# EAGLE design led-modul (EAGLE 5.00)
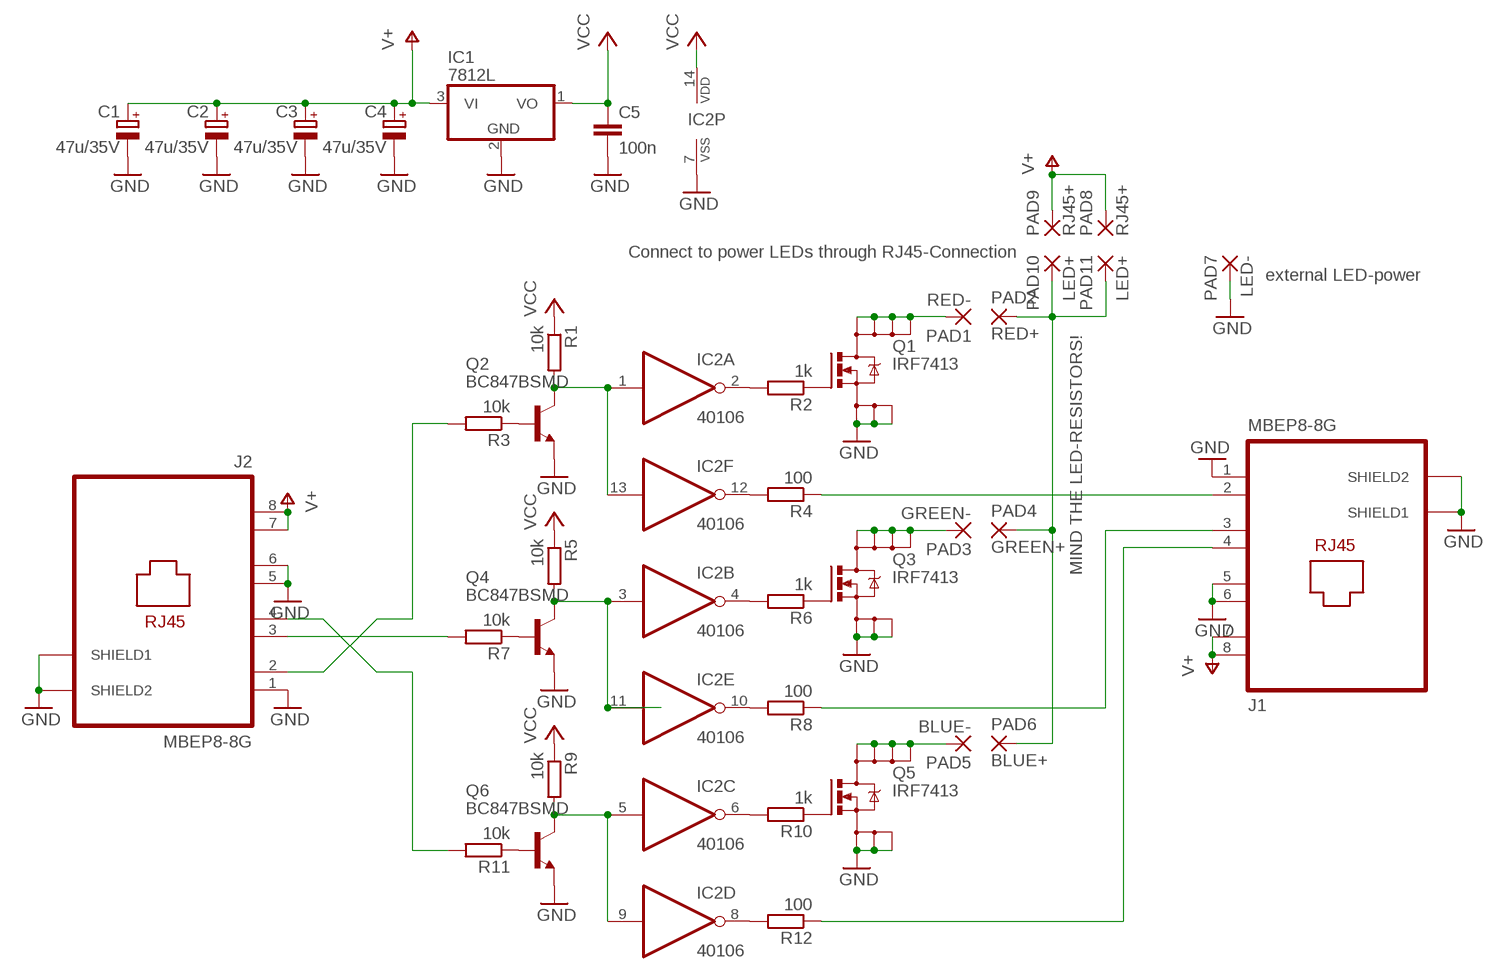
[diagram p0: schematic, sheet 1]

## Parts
C1  47u/35V  CPOL-EUE2-5  [E2-5]
C2  47u/35V  CPOL-EUE2-5  [E2-5]
C3  47u/35V  CPOL-EUE2-5  [E2-5]
C4  47u/35V  CPOL-EUE2-5  [E2-5]
C5  100n  C-EUC1206  [C1206]
IC1  7812L  [TO92]
IC2  40106  4584D  [SO14]
J1  MBEP8-8G  [MBEP8-8G]
J2  MBEP8-8G  [MBEP8-8G]
PAD1  RED-  2,54/1,1  [2,54/1,1]
PAD2  RED+  2,54/1,1  [2,54/1,1]
PAD3  GREEN-  2,54/1,1  [2,54/1,1]
PAD4  GREEN+  2,54/1,1  [2,54/1,1]
PAD5  BLUE-  2,54/1,1  [2,54/1,1]
PAD6  BLUE+  2,54/1,1  [2,54/1,1]
PAD7  LED-  2,54/1,1  [2,54/1,1]
PAD8  RJ45+  2,54/1,1  [2,54/1,1]
PAD9  RJ45+  2,54/1,1  [2,54/1,1]
PAD10  LED+  2,54/1,1  [2,54/1,1]
PAD11  LED+  2,54/1,1  [2,54/1,1]
Q1  IRF7413  [SO08]
Q2  BC847BSMD  [SOT23]
Q3  IRF7413  [SO08]
Q4  BC847BSMD  [SOT23]
Q5  IRF7413  [SO08]
Q6  BC847BSMD  [SOT23]
R1  10k  R-EU_R1206  [R1206]
R2  1k  R-EU_R1206  [R1206]
R3  10k  R-EU_R1206  [R1206]
R4  100  R-EU_R1206  [R1206]
R5  10k  R-EU_R1206  [R1206]
R6  1k  R-EU_R1206  [R1206]
R7  10k  R-EU_R1206  [R1206]
R8  100  R-EU_R1206  [R1206]
R9  10k  R-EU_R1206  [R1206]
R10  1k  R-EU_R1206  [R1206]
R11  10k  R-EU_R1206  [R1206]
R12  100  R-EU_R1206  [R1206]

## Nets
GND: C1.- C2.- C3.- C4.- C5.2 IC1.2(GND) IC2.7(P:VSS) J1.1 J1.5 J1.6 J1.S1(SHIELD1) J1.S2(SHIELD2) J2.1 J2.5 J2.6 J2.S1(SHIELD1) J2.S2(SHIELD2) PAD7.1(P) Q1.1(S) Q1.2(S) Q1.3(S) Q2.2(E) Q3.1(S) Q3.2(S) Q3.3(S) Q4.2(E) Q5.1(S) Q5.2(S) Q5.3(S) Q6.2(E)
LED+: PAD2.1(P) PAD4.1(P) PAD6.1(P) PAD10.1(P) PAD11.1(P)
N$1: Q2.1(B) R3.1
N$2: Q1.4(G) R2.1
N$3: IC2.2(A:O) R2.2
N$4: J2.2 R3.2
N$5: PAD1.1(P) Q1.5(D) Q1.6(D) Q1.7(D) Q1.8(D)
N$6: IC2.1(A:I) IC2.13(F:I) Q2.3(C) R1.2
N$7: Q4.1(B) R7.1
N$8: IC2.4(B:O) R6.2
N$9: Q3.4(G) R6.1
N$10: IC2.3(B:I) IC2.11(E:I) Q4.3(C) R5.2
N$11: IC2.6(C:O) R10.2
N$12: Q5.4(G) R10.1
N$13: Q6.1(B) R11.1
N$14: PAD3.1(P) Q3.5(D) Q3.6(D) Q3.7(D) Q3.8(D)
N$15: PAD5.1(P) Q5.5(D) Q5.6(D) Q5.7(D) Q5.8(D)
N$17: J2.4 R11.2
N$18: J2.3 R7.2
N$19: J1.2 R4.1
N$20: J1.3 R8.1
N$21: J1.4 R12.1
N$22: IC2.12(F:O) R4.2
N$23: IC2.10(E:O) R8.2
N$24: IC2.8(D:O) R12.2
N$25: IC2.5(C:I) IC2.9(D:I) Q6.3(C) R9.2
V+: C1.+ C2.+ C3.+ C4.+ IC1.3(VI) J1.7 J1.8 J2.7 J2.8 PAD8.1(P) PAD9.1(P)
VCC: C5.1 IC1.1(VO) IC2.14(P:VDD) R1.1 R5.1 R9.1

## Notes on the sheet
- Connect to power LEDs through RJ45-Connection
- external LED-power
- MIND THE LED-RESISTORS!

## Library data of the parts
C1-C4 = rcl:CPOL-EU: POLARIZED CAPACITOR, European symbol
C5 = rcl:C-EU: CAPACITOR, European symbol
IC1 = linear:78*: Positive VOLTAGE REGULATOR Source: http://cache.national.com/ds/LM/LM78L05.pdf http://www.fairchildsemi.com/ds/LM/LM7805.pdf
IC2 = 45xx:4584: Hex SCHMITT TRIGGER (74C14)
J1 J2 = own:MBEP8-8G: Distributor: Reichelt.de
PAD1-PAD11 = wirepad:2,54/1,1: THROUGH-HOLE PAD
Q1 Q3 Q5 = own:IRF7413: HEXFET Power MOSFET
Q2 Q4 Q6 = transistor-npn:BC847*: NPN Transistor
R1-R12 = rcl:R-EU_: RESISTOR, European symbol

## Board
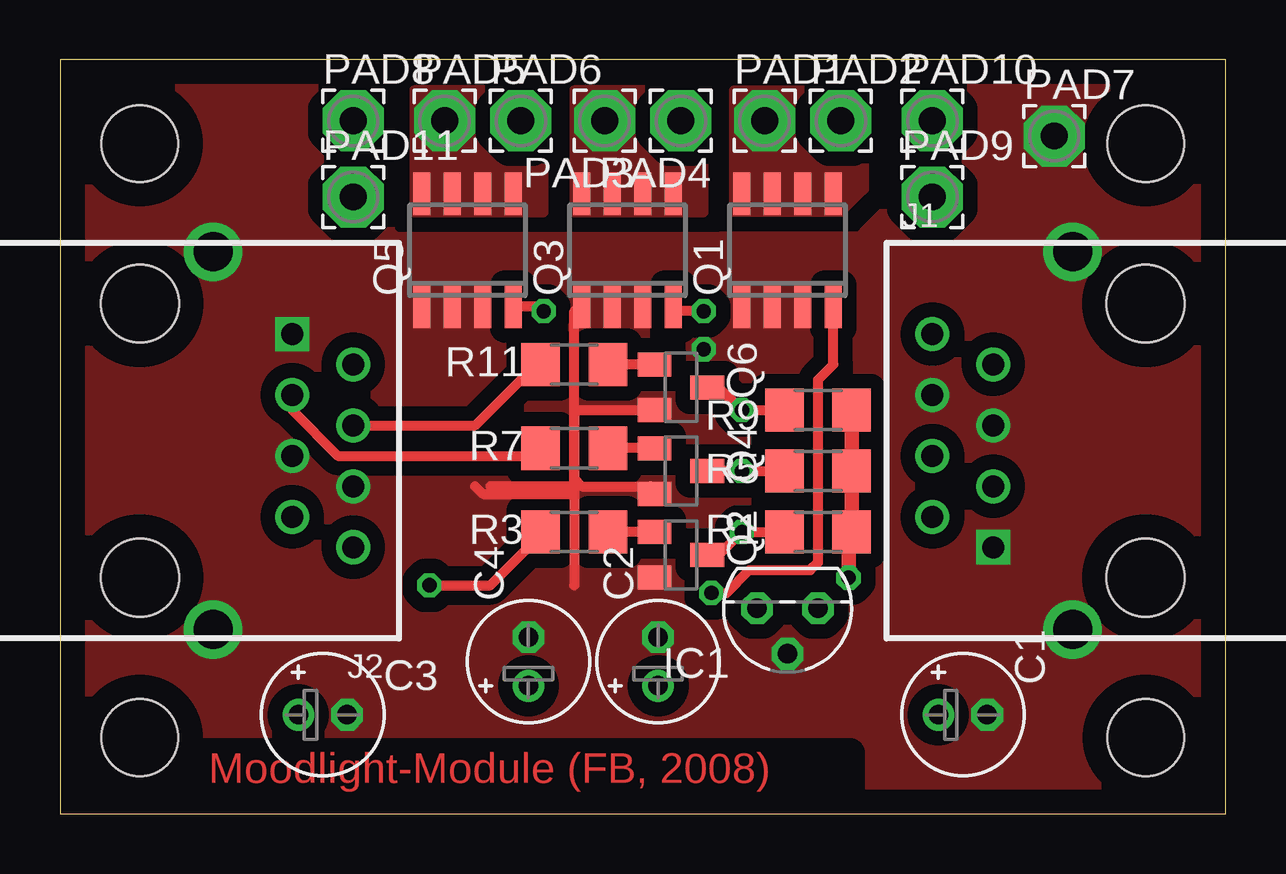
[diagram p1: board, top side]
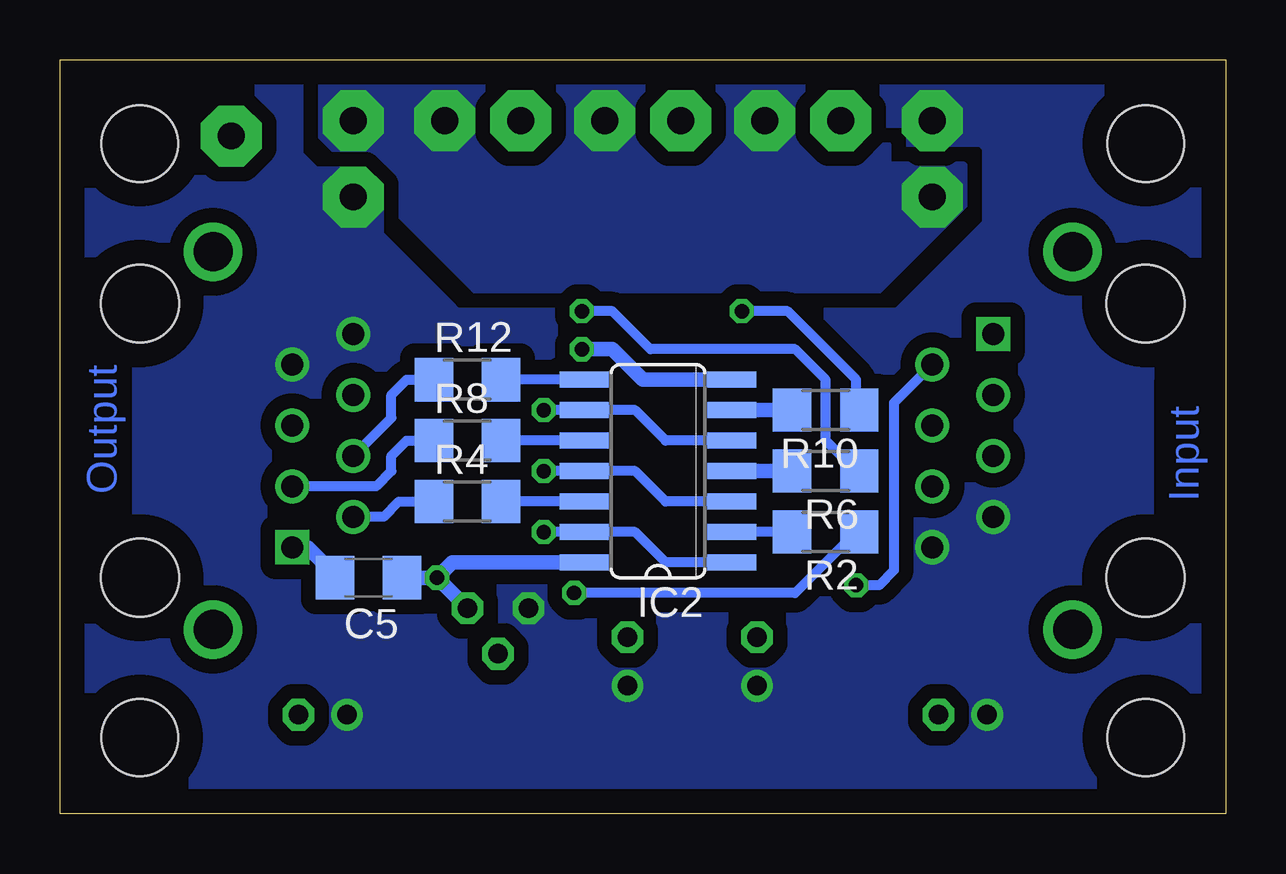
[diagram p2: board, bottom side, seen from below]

Size 48.56 x 31.42 mm. Coordinates in mm from the lower left corner, seen from the top.
Outline: 0,0 48.56,0 48.56,31.42 0,31.42 0,0
Copper layers (1*16): Top 0.035mm / dielectric 1.5mm / Bottom 0.035mm
Design rules "default": minimum track width 10mil, minimum drill 24mil, track to track 8mil, track to pad 8mil, pad to pad 8mil, via to via 8mil, smd to smd 8mil, copper to edge 40mil, drill to drill 8mil, minimum pad ring 10mil, minimum via ring 8mil, stop-mask expansion 4mil, vias tented up to drill 0mil, thermal gap 10mil
Holes 3.2 mm at 45.24,3.17 45.24,27.94 3.33,27.94 3.33,3.17

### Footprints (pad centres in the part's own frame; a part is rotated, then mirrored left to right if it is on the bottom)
E2-5 = drill 0.813 pad 1.27 round: + -1.016,0 | drill 0.813 pad 1.27 octagon: - 1.016,0
C1206 = smd 1.6 x 1.8: 1 -1.4,0; 2 1.4,0
TO92 = drill 0.813 octagon: 1 -1.27,0; 2 0,1.905; 3 1.27,0
SO14 = smd 0.66 x 2.032: 1 -3.81,-3.073; 2 -2.54,-3.073; 3 -1.27,-3.073; 4 0,-3.073; 5 1.27,-3.073; 6 2.54,-3.073; 7 3.81,-3.073; 8 3.81,3.073; 9 2.54,3.073; 10 1.27,3.073; 11 0,3.073; 12 -1.27,3.073; 13 -2.54,3.073; 14 -3.81,3.073
MBEP8-8G = drill 0.914 square: 1 4.445,-6.35 | drill 0.914 round: 2 3.175,-8.89; 3 1.905,-6.35; 4 0.635,-8.89; 5 -0.635,-6.35; 6 -1.905,-8.89; 7 -3.175,-6.35; 8 -4.445,-8.89 | drill 1.626 round: S1 -7.874,-3.048; S2 7.874,-3.048 | hole 3.251: -5.715,0; 5.715,0
2,54/1,1 = drill 1.118 pad 2.54 octagon: 1 0,0
SO08 = smd 0.72 x 1.78: 1 -1.905,-2.35; 2 -0.635,-2.35; 3 0.635,-2.35; 4 1.905,-2.35; 5 1.905,2.35; 6 0.635,2.35; 7 -0.635,2.35; 8 -1.905,2.35
SOT23 = smd 1 x 1.4: 1 -0.95,-1.1; 2 0.95,-1.1; 3 0,1.1
R1206 = smd 1.6 x 1.8: 1 -1.4,0; 2 1.4,0

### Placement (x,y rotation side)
C1  37.62,4.12 0 top
C2  24.92,6.34 90 top
C3  10.95,4.12 0 top
C4  19.52,6.34 90 top
C5  35.71,9.84 180 bottom
IC1  30.32,8.57 180 top
IC2  23.65,14.28 90 bottom
J1  45.24,15.55 270 top
J2  3.33,15.55 90 top
PAD1  29.36,28.89 0 top
PAD2  32.54,28.89 0 top
PAD3  22.7,28.89 180 top
PAD4  25.87,28.89 180 top
PAD5  16.03,28.89 0 top
PAD6  19.2,28.89 0 top
PAD7  41.43,28.25 0 top
PAD8  12.22,28.89 0 top
PAD9  36.35,25.71 0 top
PAD10  36.35,28.89 0 top
PAD11  12.22,25.71 0 top
Q1  30.32,23.49 0 top
Q2  25.87,10.79 270 top
Q3  23.65,23.49 0 top
Q4  25.87,14.28 270 top
Q5  16.98,23.49 0 top
Q6  25.87,17.78 270 top
R1  31.59,11.74 180 top
R2  16.66,11.74 180 bottom
R3  21.43,11.74 180 top
R4  31.59,13.01 0 bottom
R5  31.59,14.28 180 top
R6  16.66,14.28 180 bottom
R7  21.43,15.23 180 top
R8  31.59,15.55 0 bottom
R9  31.59,16.82 180 top
R10  16.66,16.82 180 bottom
R11  21.43,18.73 180 top
R12  31.59,18.09 0 bottom

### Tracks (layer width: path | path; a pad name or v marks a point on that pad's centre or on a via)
GND  (via drill 0.6)
  Top 0.406: 21.43,16.82 Q6.2 | 21.43,16.82 21.43,16.19 21.43,13.96 21.74,13.65 24.6,13.65 24.91,13.33 | 24.91,13.33 24.92,13.33 | 24.91,13.33 Q4.2 | Q3.1 21.74,21.27 21.43,20.95 21.43,16.82 | 21.43,16.82 21.43,9.52 | 21.43,13.65 17.93,13.65 | 21.43,16.82 21.43,13.65 | 21.43,13.65 21.43,13.33 17.62,13.33 17.3,13.65
  Bottom 0.61: 20.47,18.09 IC2.7 24.28,18.09 25.55,19.36 v26.82,19.36 | C5.2 36.98,9.84 38.25,11.11 J1.1
  pour Top (isolate 0.61, rank 6, no thermals): -3.02,33.97 -3.02,-2.86 51.91,-2.86 51.91,33.97
LED+
  pour Bottom (isolate 0.61, rank 3, no thermals): 14.12,32.38 37.62,32.38 37.62,28.25 31.27,21.9 14.44,21.9 10.95,25.39 10.95,26.98 14.12,26.98
N$1
  Top 0.406: Q2.1 24.91,11.74 24.92,11.74 R3.1
N$2  (via drill 0.6)
  Top 0.406: Q1.4 32.22,18.73 31.59,18.09 31.59,10.47 31.27,10.15 28.73,10.15 27.78,9.2 v27.14,9.2
  Bottom 0.406: R2.1 15.39,11.74 17.93,9.2 v27.14,9.2
N$3
  Bottom 0.406: R2.2 IC2.2
N$4  (via drill 0.6)
  Top 0.406: R3.2 20.16,11.74 17.93,9.52 v15.39,9.52
  Bottom 0.406: J2.2 13.81,17.14 13.81,10.15 14.44,9.52 v15.39,9.52
N$5
  pour Top (isolate 0.61, no thermals): 28.09,25.08 28.09,30.16 33.49,30.16 33.49,26.03 32.54,25.08
N$6  (via drill 0.6)
  Top 0.406: Q2.3 27.46,10.79 v28.41,11.74 R1.2
  Bottom 0.406: IC2.1 23.33,10.47 24.6,11.74 IC2.13 v28.41,11.74
N$7
  Top 0.406: Q4.1 24.6,15.23 R7.1
N$8
  Bottom 0.61: R6.2 IC2.4
N$9  (via drill 0.6)
  Top 0.406: Q3.4 25.55,20.95 v26.82,20.95
  Bottom 0.406: R6.1 15.39,14.28 16.66,15.55 16.66,18.09 17.93,19.36 23.96,19.36 25.55,20.95 v26.82,20.95
N$10  (via drill 0.6)
  Top 0.406: R5.2 v28.41,14.28 Q4.3 26.82,14.28
  Bottom 0.406: IC2.3 23.33,13.01 24.6,14.28 IC2.11 v28.41,14.28
N$11
  Bottom 0.61: R10.2 IC2.6
N$12  (via drill 0.6)
  Top 0.406: Q5.4 19.96,21.14 v20.16,20.95
  Bottom 0.406: v20.16,20.95 18.25,20.95 15.39,18.09 15.39,16.82 R10.1
N$13
  Top 0.406: Q6.1 24.91,18.73 24.92,18.73 R11.1
N$14
  pour Top (isolate 0.61, no thermals): 21.43,30.16 21.43,25.08 26.82,25.08 26.82,30.16
N$15
  pour Top (isolate 0.61, no thermals): 14.76,30.16 14.76,25.08 20.16,25.08 20.16,30.16
N$17
  Top 0.406: 20.16,18.73 R11.2 19.84,18.73 17.3,16.19 J2.4
N$18
  Top 0.406: J2.3 9.68,16.82 11.58,14.92 19.84,14.92 R7.2
N$19
  Bottom 0.406: J1.2 35.08,12.38 34.44,13.01 R4.1
N$20
  Bottom 0.406: R8.1 34.12,15.55 34.76,14.92 34.76,14.28 35.4,13.65 J1.3
N$21
  Bottom 0.406: J1.4 34.76,16.51 34.76,17.46 34.12,18.09 R12.1
N$22
  Bottom 0.406: IC2.12 R4.2
N$23
  Bottom 0.406: IC2.10 R8.2
N$24
  Bottom 0.406: IC2.8 R12.2
N$25  (via drill 0.6)
  Top 0.406: Q6.3 27.46,17.78 v28.41,16.82 R9.2
  Bottom 0.406: IC2.5 23.33,15.55 24.6,16.82 IC2.9 v28.41,16.82
V+
  pour Bottom (isolate 0.61, rank 6, no thermals): 50,-1.27 -1.44,-1.27 -1.44,32.38 50,32.38
VCC  (via drill 0.6)
  Top 0.61: R9.1 32.98,14.47 33.17,14.28 R5.1 32.98,11.93 33.17,11.74 R1.1 32.86,11.74 v32.86,9.84
  Bottom 0.61: IC2.14 32.22,10.47 v32.86,9.84 | v32.86,9.84 C5.1 | v32.86,9.84 IC1.1

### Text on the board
Top: Moodlight-Module (FB, 2008)
Bottom: Output | Input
